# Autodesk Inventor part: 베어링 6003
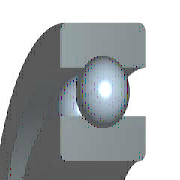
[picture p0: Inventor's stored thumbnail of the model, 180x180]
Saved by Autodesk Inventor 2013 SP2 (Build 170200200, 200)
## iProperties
Created: 2012-02
Part Number: 베어링 6003
Material: 강철, 연강
Description: 깊은 그루브 볼 베어링
Document SubType Name: Modeling
Standard: KS B 2023
Designer: mduedu
Standards Organization: KS
Language: ko-KR
Size Designation: 6003 - 17 x 35 x 10
Categories: <MemberInstance><Categories><Category DisplayName="샤프트 부품" InternalName="7f7aeb1f-a693-4053-b835-cee3144e0d98" Mnemonic="SHFT"><Category DisplayName="베어링" Inter
Density: 1 g/cm^3
IsCustomPart: 1
Author: mduedu
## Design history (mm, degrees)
sketch "스케치" dims "d0" = 4.68 (= -0.26 x WD + 0.26 x BD)
  geometry: L1 (2.66, 13)-(7.34, 13); L2 (5, 13)-(5, 10.66); L3 (5, 13)-(5, 15.34); L4 (3.261, 11.434)-(0, 11.434); L5 (0, 8.5)-(10, 8.5); L6 (3.261, 14.566)-(0, 14.566); L7 (0, 17.5)-(10, 17.5); L8 (10, 8.5)-(10, 11.434); L9 (6.739, 11.434)-(10, 11.434); L10 (6.739, 14.566)-(10, 14.566); L11 (10, 17.5)-(10, 14.566); L12 (-1.4, 0)-(8.4, 0) reference; L13 (0, -0.3)-(0, 5.3) reference
  constraints: 22 end point, 4 point on line, 2 collinear, 2 perpendicular, 2 symmetric about line, 1 midpoint, 1 parallel, 14 other
  dimensions: "d9" = 17 diameter of L5 L12 (= WD); "d11" = 35 diameter of L7 L12 (= BD); "d12" = 10 distance between parallel lines of L8 L13 (= KB); "d13" = 22.868 diameter of L9 L12 (= 0.326 x BD + 0.674 x WD)
revolve "본체" stored, may be unused: angle "d6" = 90 deg
revolve "볼" stored, may be unused: angle "d7" = 90 deg
pattern_circular "IDS_ARRAYBALL[SIMPL:T]" dims angle "d3" = 360 deg
body "Solid1"
fillet "모깎기1" dims "d1" = 0.3 (= KRS)
other parameters: "WD" = 17 [user parameter; used in 5 equation terms], "BD" = 35 [user parameter; used in 5 equation terms], "KB" = 10 [user parameter; used in 1 equation term], "KRS" = 0.3 [user parameter; used in 1 equation term], "d4" = 0, "d5" = 0, "d8" = 0, "d14" = 0, "d15" = 0, "BBA" = 0 [user parameter], "BC0" = 3250000 [user parameter], "BC" = 6050000 [user parameter], "BR" = 17.5 (= 0.5 x BD) [user parameter], "WR" = 8.5 (= 0.5 x WD) [user parameter]
